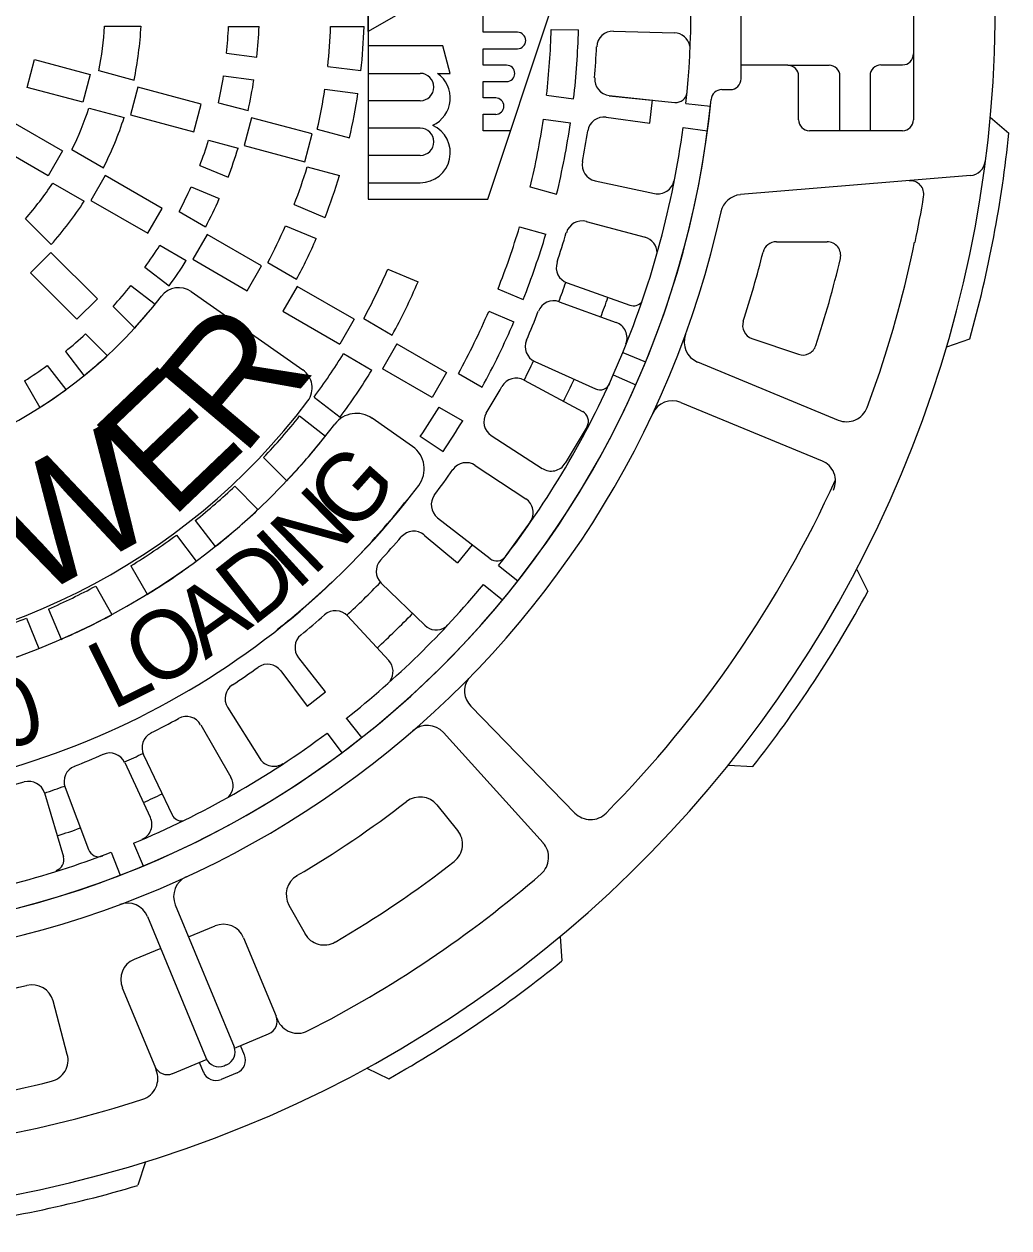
# Model space of a CAD drawing. Extents: x -7.1 to 10, y -5 to 6.
# Drawn here: x -1.07 to -0.132, y -0.445 to 0.702 of the extents above; entities that cross this region are included whole.
import ezdxf

# ---------------------------------------------------------------- set-up
doc = ezdxf.new("R2010")
doc.units = 0
doc.layers.add('Level 1', color=7, linetype='Continuous')

msp = doc.modelspace()

# ---------------------------------------------------------------- linework, layer by layer
at = {"layer": 'Level 1'}
for p, q in [((-0.2233, 0.824), (-0.2233, 0.6105)), ((-0.2233, 0.7612), (-0.2233, 0.6732)), ((-0.7424, 0.7172), (-0.7424, 0.5349)), ((-0.6287, 0.5349), (-0.5679, 0.7172)), ((-0.3874, 0.6496), (-0.3874, 0.7172)), ((-0.9934, 0.6998), (-0.9588, 0.6997)), ((-0.8755, 0.6995), (-0.8464, 0.6995)), ((-0.633, 0.6938), (-0.633, 0.7094)), ((-0.7782, 0.6993), (-0.7464, 0.6992)), ((-0.6003, 0.6938), (-0.633, 0.6938)), ((-0.5682, 0.6966), (-0.5422, 0.6963)), ((-0.5089, 0.6949), (-0.4511, 0.6933)), ((-0.633, 0.6782), (-0.6003, 0.6782)), ((-0.633, 0.6625), (-0.633, 0.6782)), ((-1.0671, 0.6414), (-1.06, 0.6679)), ((-1.06, 0.6679), (-1.0071, 0.6537)), ((-0.8773, 0.6741), (-0.8485, 0.6703)), ((-1.0071, 0.6537), (-1.0142, 0.6273)), ((-0.9988, 0.6573), (-0.9654, 0.6483)), ((-0.7809, 0.6614), (-0.7494, 0.6573)), ((-0.6107, 0.6625), (-0.633, 0.6625)), ((-0.3431, 0.6625), (-0.3874, 0.6625)), ((-0.3431, 0.6625), (-0.3037, 0.6625)), ((-0.2543, 0.6628), (-0.2338, 0.6628)), ((-0.8801, 0.6524), (-0.8513, 0.6486)), ((-0.633, 0.6469), (-0.6107, 0.6469)), ((-0.633, 0.6313), (-0.633, 0.6469)), ((-0.3327, 0.6105), (-0.3327, 0.6521)), ((-0.2933, 0.6), (-0.2933, 0.6521)), ((-0.2647, 0.6524), (-0.2647, 0.6)), ((-1.0142, 0.6273), (-1.0671, 0.6414)), ((-0.9618, 0.6415), (-0.9689, 0.6151)), ((-0.9014, 0.6254), (-0.9618, 0.6415)), ((-0.7837, 0.6397), (-0.7522, 0.6356)), ((-0.6211, 0.6313), (-0.633, 0.6313)), ((-0.5727, 0.634), (-0.5469, 0.6306)), ((-0.513, 0.6336), (-0.4719, 0.6292)), ((-0.513, 0.6334), (-0.4504, 0.627)), ((-0.4057, 0.6392), (-0.3978, 0.6392)), ((-1.0082, 0.6217), (-0.9749, 0.6127)), ((-0.9085, 0.5989), (-0.9014, 0.6254)), ((-0.8849, 0.6268), (-0.8568, 0.6192)), ((-0.4743, 0.6074), (-0.4719, 0.6294)), ((-0.44, 0.626), (-0.4167, 0.6235)), ((-1.0809, 0.6082), (-1.0334, 0.5808)), ((-0.9689, 0.6151), (-0.9085, 0.5989)), ((-0.8536, 0.6125), (-0.8606, 0.5861)), ((-0.7957, 0.597), (-0.8536, 0.6125)), ((-0.633, 0.6157), (-0.6211, 0.6157)), ((-0.633, 0.6), (-0.633, 0.6157)), ((-0.5757, 0.6112), (-0.5499, 0.6077)), ((-0.5159, 0.613), (-0.4743, 0.6074)), ((-0.1502, 0.6131), (-0.1325, 0.5979)), ((-0.8028, 0.5706), (-0.7957, 0.597)), ((-0.791, 0.6016), (-0.7603, 0.5934)), ((-0.607, 0.6), (-0.633, 0.6)), ((-0.4427, 0.6032), (-0.4195, 0.6)), ((-0.2338, 0.6), (-0.3223, 0.6)), ((-0.8945, 0.591), (-0.8663, 0.5834)), ((-0.8606, 0.5861), (-0.8028, 0.5706)), ((-1.0471, 0.5571), (-1.0945, 0.5845)), ((-1.0334, 0.5808), (-1.0471, 0.5571)), ((-1.0245, 0.5821), (-0.9945, 0.5648)), ((-0.9028, 0.5669), (-0.8759, 0.5558)), ((-0.8005, 0.5656), (-0.7699, 0.5573)), ((-0.9928, 0.5573), (-1.0065, 0.5337)), ((-0.9387, 0.5261), (-0.9928, 0.5573)), ((-0.5264, 0.5524), (-0.4699, 0.5403)), ((-0.1692, 0.5574), (-0.388, 0.5392)), ((-1.0428, 0.5502), (-1.0129, 0.5329)), ((-0.9111, 0.5467), (-0.8842, 0.5356)), ((-0.5882, 0.5465), (-0.5631, 0.5396)), ((-1.0065, 0.5337), (-0.9523, 0.5024)), ((-0.813, 0.5297), (-0.7836, 0.5175)), ((-0.7424, 0.5349), (-0.6287, 0.5349)), ((-1.0688, 0.5162), (-1.0443, 0.4917)), ((-0.9523, 0.5024), (-0.9387, 0.5261)), ((-0.9224, 0.5232), (-0.8972, 0.5086)), ((-0.8213, 0.5095), (-0.7919, 0.4973)), ((-0.5984, 0.5086), (-0.5733, 0.5016)), ((-0.5348, 0.5137), (-0.4789, 0.4987)), ((-0.8958, 0.5013), (-0.9095, 0.4776)), ((-0.8439, 0.4714), (-0.8958, 0.5013)), ((-0.3539, 0.4943), (-0.3056, 0.4943)), ((-1.0446, 0.484), (-1.0639, 0.4647)), ((-1.0003, 0.4398), (-1.0446, 0.484)), ((-0.9408, 0.4911), (-0.9157, 0.4765)), ((-0.9095, 0.4776), (-0.8576, 0.4477)), ((-0.8576, 0.4477), (-0.8439, 0.4714)), ((-0.8381, 0.4745), (-0.8106, 0.4586)), ((-1.0639, 0.4647), (-1.0197, 0.4205)), ((-0.9551, 0.47), (-0.9321, 0.4523)), ((-0.7238, 0.4683), (-0.695, 0.4562)), ((-0.9684, 0.4526), (-0.9453, 0.4349)), ((-0.81, 0.4518), (-0.8237, 0.4281)), ((-0.7559, 0.4206), (-0.81, 0.4518)), ((-0.6189, 0.4494), (-0.5949, 0.4394)), ((-0.553, 0.4551), (-0.4933, 0.4339)), ((-1.0197, 0.4205), (-1.0003, 0.4398)), ((-0.9109, 0.4468), (-0.8046, 0.3724)), ((-0.5606, 0.4372), (-0.5063, 0.4175)), ((-0.9854, 0.4328), (-0.9648, 0.4122)), ((-0.8237, 0.4281), (-0.7696, 0.3969)), ((-0.8237, 0.4281), (-0.7696, 0.3969)), ((-0.6277, 0.4281), (-0.6037, 0.418)), ((-0.7559, 0.4206), (-0.7696, 0.3969)), ((-0.7467, 0.4211), (-0.7197, 0.4054)), ((-1.0115, 0.4066), (-0.991, 0.3859)), ((-0.3773, 0.4022), (-0.3329, 0.3871)), ((-0.1917, 0.3943), (-0.1697, 0.4019)), ((-1.0308, 0.3899), (-1.0131, 0.3668)), ((-0.7153, 0.3971), (-0.729, 0.3734)), ((-0.7153, 0.3971), (-0.6679, 0.3698)), ((-0.766, 0.3878), (-0.739, 0.372)), ((-0.5838, 0.3803), (-0.5261, 0.3541)), ((-0.5092, 0.3677), (-0.5001, 0.3888)), ((-0.5001, 0.3888), (-0.4785, 0.3799)), ((-0.4288, 0.3798), (-0.2949, 0.3244)), ((-1.0481, 0.3766), (-1.0304, 0.3535)), ((-0.6816, 0.3461), (-0.729, 0.3734)), ((-0.6679, 0.3698), (-0.6816, 0.3461)), ((-0.6566, 0.3688), (-0.6341, 0.3557)), ((-0.5092, 0.3677), (-0.4878, 0.3582)), ((-1.0696, 0.3618), (-1.0551, 0.3366)), ((-0.594, 0.3626), (-0.5383, 0.3325)), ((-0.2674, 0.3365), (-0.2582, 0.3621)), ((-0.794, 0.3464), (-0.7692, 0.3274)), ((-0.6751, 0.3367), (-0.6525, 0.3238)), ((-0.4448, 0.3413), (-0.3104, 0.2857)), ((-0.8078, 0.3284), (-0.7831, 0.3093)), ((-0.7002, 0.2993), (-0.7386, 0.3262)), ((-0.6253, 0.3097), (-0.5767, 0.2784)), ((-0.5341, 0.3183), (-0.5549, 0.2833)), ((-0.6929, 0.309), (-0.6712, 0.2946)), ((-0.8421, 0.2888), (-0.82, 0.2666)), ((-0.6405, 0.2813), (-0.5923, 0.2494)), ((-0.8693, 0.2616), (-0.8474, 0.2393)), ((-0.6764, 0.2315), (-0.6265, 0.1925)), ((-0.9071, 0.2288), (-0.8881, 0.204)), ((-0.6118, 0.1944), (-0.5881, 0.2275)), ((-0.9251, 0.215), (-0.9062, 0.1901)), ((-0.6891, 0.215), (-0.6574, 0.1885)), ((-0.6434, 0.2057), (-0.6574, 0.1885)), ((-0.9685, 0.1856), (-0.9529, 0.1585)), ((-0.6184, 0.1859), (-0.5999, 0.1715)), ((-0.2773, 0.1821), (-0.2668, 0.1613)), ((-1.0018, 0.1664), (-0.9865, 0.1392)), ((-0.7301, 0.1692), (-0.6886, 0.129)), ((-0.6328, 0.168), (-0.6147, 0.1531)), ((-1.0468, 0.1445), (-1.0349, 0.1157)), ((-0.7622, 0.1379), (-0.7229, 0.0954)), ((-1.0678, 0.1358), (-1.0559, 0.1069)), ((-0.8089, 0.098), (-0.7833, 0.0655)), ((-0.8257, 0.0857), (-0.8006, 0.052)), ((-0.8006, 0.052), (-0.7831, 0.0657)), ((-0.8763, 0.0509), (-0.8455, 0.002)), ((-0.5458, -0.0498), (-0.6449, 0.052)), ((-0.7633, 0.0404), (-0.7488, 0.022)), ((-0.9019, 0.0343), (-0.8731, -0.0158)), ((-0.7816, 0.0264), (-0.7675, 0.0076)), ((-0.6707, 0.0269), (-0.576, -0.0782)), ((-0.9563, 0.0057), (-0.9291, -0.0515)), ((-0.9743, -0.0016), (-0.9499, -0.0539)), ((-0.3994, -0.0041), (-0.3762, -0.0055)), ((-1.0507, -0.0307), (-1.0326, -0.0914)), ((-1.031, -0.0254), (-1.0087, -0.0847)), ((-0.677, -0.0421), (-0.6573, -0.0663)), ((-0.9658, -0.0785), (-0.9568, -0.1002)), ((-0.9871, -0.0871), (-0.9787, -0.1089)), ((-0.9262, -0.1374), (-0.8702, -0.2725)), ((-0.9526, -0.1485), (-0.8967, -0.2835)), ((-0.8179, -0.1376), (-0.8026, -0.1649)), ((-0.9136, -0.1678), (-0.8883, -0.1573)), ((-0.8611, -0.1686), (-0.8302, -0.2432)), ((-0.5598, -0.1674), (-0.558, -0.1907)), ((-0.94, -0.1788), (-0.9653, -0.1892)), ((-0.9766, -0.2164), (-0.9457, -0.291)), ((-1.0289, -0.2797), (-1.0425, -0.2288)), ((-0.8297, -0.2447), (-0.8288, -0.2468)), ((-0.8697, -0.2737), (-0.8373, -0.2602)), ((-0.8603, -0.2803), (-0.864, -0.2713)), ((-0.8962, -0.2846), (-0.9287, -0.2981)), ((-0.9457, -0.291), (-0.9442, -0.2946)), ((-0.8994, -0.2965), (-0.9031, -0.2875)), ((-0.8673, -0.2973), (-0.8824, -0.3035)), ((-0.8784, -0.2901), (-0.8785, -0.2901)), ((-0.7438, -0.2927), (-0.7229, -0.3029)), ((-0.9544, -0.3822), (-0.9617, -0.4044))]:
    msp.add_line(p, q, dxfattribs=at)
for points in [[(-0.7424, 0.7807), (-0.7424, 0.8108), (-0.6643, 0.7657), (-0.6643, 0.7397), (-0.7424, 0.6946), (-0.7424, 0.7246)], [(-0.6765, 0.6547), (-0.6643, 0.6547), (-0.6713, 0.6808), (-0.7424, 0.6808), (-0.7424, 0.6547), (-0.6929, 0.6547)], [(-0.7424, 0.6287), (-0.7424, 0.6027), (-0.6929, 0.6027)], [(-0.6929, 0.6287), (-0.7424, 0.6287)], [(-0.6929, 0.5766), (-0.7424, 0.5766), (-0.7424, 0.5506), (-0.6929, 0.5506)]]:
    msp.add_lwpolyline(points, dxfattribs=at)
for centre, radius, start, end in [((-1.2973, 0.7173), 1.1516, 195.0717, 189.1227), ((-1.2971, 0.7172), 0.862, 353.922, 6.078), ((-1.2971, 0.7172), 0.3042, 348.6342, 356.7065), ((-1.2971, 0.7172), 0.3388, 348.2633, 357.0305), ((-1.2971, 0.7172), 0.422, 354.1323, 357.593), ((-1.2971, 0.7172), 0.4511, 354.027, 357.7407), ((-1.2971, 0.7172), 0.5192, 353.8266, 358.0217), ((-1.2971, 0.7172), 0.551, 353.7501, 358.129), ((-0.6003, 0.686), 0.00781, 269.9991, 89.9991), ((-1.2971, 0.7172), 0.7292, 353.4475, 358.3753), ((-1.2971, 0.7172), 0.7552, 353.415, 358.4128), ((-0.5093, 0.6793), 0.0156, 88.389, 177.2537), ((-0.4515, 0.6777), 0.0156, 11.1758, 88.389), ((-1.297, 0.7171), 0.7729, 355.0578, 357.2537), ((-0.2338, 0.6732), 0.0104, 270, 0), ((-0.6929, 0.6417), 0.013, 270, 90), ((-0.6929, 0.6313), 0.0286, 294.62, 54.9032), ((-0.6107, 0.6547), 0.00781, 269.9991, 89.9991), ((-0.3431, 0.6521), 0.0104, 0, 90), ((-0.3037, 0.6521), 0.0104, 0, 90), ((-0.2543, 0.6524), 0.0104, 90, 180), ((-1.2971, 0.7172), 0.8854, 184.6051, 354.3326), ((-1.2971, 0.7172), 0.422, 347.6194, 351.1618), ((-1.2971, 0.7172), 0.4511, 347.4503, 351.2482), ((-0.5113, 0.6492), 0.0156, 175.0578, 263.9224), ((-0.3978, 0.6496), 0.0104, 270, 0), ((-1.2971, 0.7172), 0.5192, 347.1287, 351.4124), ((-1.2971, 0.7172), 0.551, 347.0059, 351.4752), ((-0.6211, 0.6235), 0.00781, 269.9991, 89.9991), ((-0.4493, 0.6374), 0.0104, 264.177, 354.6212), ((-0.4057, 0.6288), 0.0104, 90, 174.3326), ((-1.2971, 0.7172), 0.8854, 272.6352, 354.3326), ((-1.2971, 0.7172), 0.3042, 333.6342, 341.7065), ((-1.2971, 0.7172), 0.3388, 333.2633, 342.0305), ((-1.2971, 0.7172), 0.7292, 346.4545, 351.638), ((-0.518, 0.5975), 0.0156, 82.3944, 171.2591), ((-0.3223, 0.6105), 0.0104, 180, 270), ((-0.2338, 0.6105), 0.0104, 270, 0), ((-0.6929, 0.5792), 0.0286, 270, 65.38), ((-0.6929, 0.5896), 0.013, 270, 90), ((-1.2971, 0.7172), 0.7552, 346.3995, 351.6608), ((-1.2974, 0.7173), 0.7729, 349.0632, 351.2591), ((-1.2971, 0.7172), 0.862, 337.6056, 352.3944), ((-1.2966, 0.7177), 1.1703, 344.3462, 354.1251), ((-1.2971, 0.7172), 0.9115, 188.0305, 347.6848), ((-1.2971, 0.7172), 0.422, 339.1323, 342.593), ((-1.2971, 0.7172), 0.4511, 339.027, 342.7407), ((-1.2971, 0.7172), 0.5192, 338.8266, 343.0217), ((-0.5232, 0.5677), 0.0156, 169.0632, 257.9278), ((-0.1705, 0.5729), 0.0156, 274.7589, 352.7027), ((-1.2971, 0.7172), 0.551, 338.7501, 343.129), ((-0.4666, 0.5556), 0.0156, 257.9278, 348.9856), ((-0.2265, 0.5395), 0.013, 350.5705, 94.7589), ((-1.2971, 0.7172), 0.3042, 318.6342, 326.7065), ((-1.2971, 0.7172), 0.422, 332.6194, 336.1618), ((-0.3863, 0.5184), 0.0208, 94.7589, 167.6848), ((-1.2971, 0.7172), 0.3388, 318.2633, 327.0305), ((-1.2971, 0.7172), 0.4511, 332.4503, 336.2482), ((-1.2971, 0.7173), 1.0983, 348.257, 350.5705), ((-1.2971, 0.7172), 0.5192, 332.1287, 336.4124), ((-1.2971, 0.7172), 0.7292, 338.4475, 343.3753), ((-0.5388, 0.4986), 0.0156, 74.9422, 163.8068), ((-1.2971, 0.7172), 0.551, 332.0059, 336.4752), ((-1.2971, 0.7172), 0.7552, 338.415, 343.4128), ((-1.2961, 0.7186), 0.7729, 341.6109, 343.8068), ((-0.483, 0.4836), 0.0156, 0.2442, 74.9422), ((-0.3539, 0.4813), 0.013, 90, 166.0155), ((-0.3056, 0.4813), 0.013, 346.6473, 90), ((-1.2967, 0.7161), 1.0972, 341.1743, 348.3154), ((-1.2971, 0.7172), 0.422, 324.1323, 327.593), ((-1.2967, 0.7161), 0.9586, 341.9169, 346.0155), ((-1.2971, 0.7172), 0.4511, 324.027, 327.7407), ((-0.5478, 0.4698), 0.0156, 161.6109, 250.4756), ((-1.2975, 0.7168), 1.0325, 341.862, 346.6473), ((-1.2971, 0.7172), 0.625, 331.7203, 336.5279), ((-1.2971, 0.7172), 0.422, 317.6194, 321.1618), ((-0.9229, 0.4298), 0.0208, 55, 142.4698), ((-1.2971, 0.7172), 0.6563, 331.6317, 336.5646), ((-1.2971, 0.7172), 0.7875, 339.1803, 340.5909), ((-1.2971, 0.7172), 0.4511, 217.5302, 322.4698), ((-0.5659, 0.4225), 0.0156, 70.0352, 158.8998), ((-1.2971, 0.7172), 0.8301, 339.2248, 340.5852), ((-0.4898, 0.4437), 0.0104, 250.4756, 318.3766), ((-1.2971, 0.7172), 0.4511, 317.4503, 321.2482), ((-1.2971, 0.7172), 0.7292, 331.4545, 336.638), ((-1.3016, 0.7064), 0.7729, 336.704, 338.8998), ((-1.2971, 0.7172), 0.7552, 331.3995, 336.6608), ((-0.5116, 0.4028), 0.0156, 338.9774, 70.0352), ((-0.373, 0.4145), 0.013, 161.9169, 251.149), ((-1.2971, 0.7172), 0.422, 309.1323, 312.593), ((-0.4209, 0.399), 0.0208, 160.1115, 247.5378), ((-0.5774, 0.3945), 0.0156, 156.704, 245.5686), ((-0.3287, 0.3994), 0.013, 251.149, 341.862), ((-1.2971, 0.7172), 0.4511, 309.027, 312.7407), ((-1.2971, 0.7172), 0.625, 323.6043, 328.1939), ((-1.2971, 0.7172), 0.7875, 333.2323, 334.7184), ((-1.2971, 0.7172), 0.422, 302.6194, 306.1618), ((-0.8166, 0.3553), 0.0208, 323.0153, 55), ((-1.2971, 0.7172), 0.6563, 323.552, 328.2544), ((-1.2971, 0.7172), 0.862, 321.9456, 336.078), ((-1.2881, 0.7366), 0.7729, 328.3474, 330.5433), ((-0.6015, 0.3488), 0.0156, 61.6787, 150.5433), ((-1.2971, 0.7172), 0.8301, 333.1524, 334.7577), ((-0.5218, 0.3636), 0.0104, 245.5686, 336.2781), ((-1.2971, 0.7172), 0.4511, 302.4503, 306.2482), ((-1.2971, 0.7172), 0.6224, 216.9847, 323.0153), ((-1.2971, 0.7172), 0.7292, 325.9538, 328.5455), ((-0.4528, 0.322), 0.0208, 67.5378, 154.8411), ((-0.287, 0.3437), 0.0208, 247.5378, 339.8014), ((-1.2971, 0.7172), 0.625, 316.7203, 321.5279), ((-0.7536, 0.3048), 0.026, 55, 142.8126), ((-1.2971, 0.7172), 0.7552, 325.9699, 328.6005), ((-0.6168, 0.3228), 0.0156, 148.3474, 237.2121), ((-0.5432, 0.3234), 0.0104, 330.9692, 61.6787), ((-1.2971, 0.7172), 0.6562, 217.1874, 322.8126), ((-1.2971, 0.7172), 0.6563, 316.6317, 321.5646), ((-0.7151, 0.2779), 0.026, 322.9239, 55), ((-1.2972, 0.7175), 0.7729, 323.0809, 325.2768), ((-0.6491, 0.2683), 0.0156, 56.4122, 145.2768), ((-0.5682, 0.2915), 0.0156, 237.2121, 328.2699), ((-0.3184, 0.2665), 0.0208, 335.2566, 67.5378), ((-1.2976, 0.7218), 1.0983, 315.3646, 335.5685), ((-1.2973, 0.7178), 0.7557, 217.0904, 322.9239), ((-1.2971, 0.7172), 0.625, 308.6043, 313.1939), ((-0.6668, 0.2438), 0.0156, 143.0809, 231.9456), ((-1.2974, 0.7174), 0.7552, 316.3995, 321.6608), ((-0.601, 0.2364), 0.0156, 325.3544, 56.4122), ((-1.2971, 0.7172), 0.6563, 308.552, 313.2544), ((-0.6991, 0.203), 0.0156, 50.4176, 139.2822), ((-1.2971, 0.7172), 0.625, 301.7203, 306.5279), ((-1.2968, 0.7174), 0.7729, 317.0863, 319.2822), ((-1.2971, 0.7172), 0.6563, 301.6317, 306.5646), ((-0.7192, 0.1804), 0.0156, 137.0863, 225.951), ((-0.6201, 0.2007), 0.0104, 231.9456, 322.6551), ((-1.2971, 0.7172), 0.625, 293.6043, 298.1939), ((-1.2973, 0.7175), 0.7552, 308.3235, 313.5848), ((-1.2971, 0.7172), 0.862, 308.262, 320.418), ((-1.2971, 0.7172), 0.7875, 312.7158, 315.9774), ((-1.2965, 0.7174), 1.1703, 321.8462, 331.6251), ((-1.2971, 0.7172), 0.6563, 293.552, 298.2544), ((-1.2971, 0.717), 0.7729, 309.3978, 311.5937), ((-0.7736, 0.1273), 0.0156, 42.729, 131.5937), ((-1.2971, 0.7172), 0.8301, 312.7192, 315.9733), ((-1.2971, 0.7172), 0.625, 286.7203, 291.5279), ((-0.6777, 0.1402), 0.0156, 225.951, 303.1642), ((-0.7966, 0.1077), 0.0156, 129.3978, 218.2624), ((-1.2971, 0.7172), 0.6563, 286.6317, 291.5646), ((-0.8382, 0.0763), 0.0156, 36.7344, 125.5991), ((-0.7344, 0.0848), 0.0156, 325.5158, 42.729), ((-1.2972, 0.7175), 0.7729, 303.4032, 305.5991), ((-0.8631, 0.0592), 0.0156, 123.4032, 212.2678), ((-0.6299, 0.0665), 0.0208, 145.8214, 224.2281), ((-1.2955, 0.7175), 0.7729, 296.6109, 298.8068), ((-0.9155, 0.0265), 0.0156, 29.9422, 118.8068), ((-1.2971, 0.7172), 0.862, 292.6056, 306.7344), ((-0.9422, 0.0124), 0.0156, 116.6109, 205.4756), ((-0.6862, 0.0129), 0.0208, 42.022, 131.4737), ((-1.308, 0.7128), 0.7729, 291.704, 293.8998), ((-0.9885, -0.0082), 0.0156, 25.0352, 113.8998), ((-1.2971, 0.7172), 0.7875, 294.1803, 295.5909), ((-0.8323, 0.0103), 0.0156, 212.2678, 303.3256), ((-1.0164, -0.0199), 0.0156, 111.704, 200.5686), ((-1.277, 0.7246), 0.7729, 283.3474, 285.5433), ((-1.0657, -0.0352), 0.0156, 16.6787, 105.5433), ((-0.8866, -0.0236), 0.0156, 315.2442, 29.9422), ((-1.2971, 0.7172), 0.7875, 288.2323, 289.7184), ((-1.2971, 0.7172), 0.8301, 294.2248, 295.5852), ((-1.2976, 0.7217), 0.9635, 300.3841, 307.8801), ((-0.6931, -0.0553), 0.0208, 39.1639, 127.8801), ((-0.964, -0.0606), 0.0156, 293.9774, 25.0352), ((-0.9197, -0.047), 0.0104, 205.4756, 273.3766), ((-0.5308, -0.0353), 0.0208, 224.2281, 315.3646), ((-1.2971, 0.7172), 0.8301, 288.1524, 289.7577), ((-0.6734, -0.0795), 0.0208, 307.9191, 39.1639), ((-0.5915, -0.0921), 0.0208, 310.9426, 42.022), ((-1.2971, 0.7172), 0.862, 277.6056, 291.078), ((-1.0425, -0.0944), 0.0104, 285.9692, 16.6787), ((-0.999, -0.081), 0.0104, 200.5686, 291.2781), ((-1.2976, 0.7217), 1.0365, 300.3463, 307.9191), ((-0.9069, -0.1294), 0.0208, 114.807, 202.5), ((-0.7997, -0.1275), 0.0208, 120.3841, 209.1622), ((-1.2976, 0.7218), 1.0983, 296.9323, 310.9426), ((-0.9718, -0.1564), 0.0208, 22.5, 110.3605), ((-0.8803, -0.1766), 0.0208, 22.5, 112.5), ((-0.7845, -0.1547), 0.0208, 209.1622, 300.3463), ((-0.9573, -0.2085), 0.0208, 112.5, 202.5), ((-1.2965, 0.7172), 1.1703, 299.3462, 309.1251), ((-1.2976, 0.7217), 0.9635, 276.5447, 283.807), ((-1.0626, -0.2342), 0.0208, 15.0206, 103.807), ((-0.8422, -0.2482), 0.013, 292.5, 22.5), ((-0.8096, -0.2388), 0.0208, 202.5, 296.9323), ((-0.8822, -0.2775), 0.013, 292.5706, 22.5), ((-1.049, -0.2851), 0.0208, 283.9682, 15.0206), ((-0.8846, -0.2785), 0.013, 202.5, 292.4327), ((-0.8723, -0.2852), 0.013, 292.5, 22.5), ((-0.9635, -0.3026), 0.0208, 288.0661, 22.5), ((-0.9337, -0.286), 0.013, 202.5, 292.5), ((-0.8874, -0.2915), 0.013, 202.5, 292.5), ((-1.2976, 0.7217), 1.0951, 292.4327, 292.5706), ((-1.2986, 0.7183), 1.0548, 276.5594, 283.9682), ((-1.2976, 0.7218), 1.0983, 272.2423, 288.0661), ((-1.2965, 0.7169), 1.1703, 276.8462, 286.6251)]:
    msp.add_arc(centre, radius, start, end, dxfattribs=at)

# ---------------------------------------------------------------- texts
for s, height, rotation, p in [('R', 0.1144, 49.9036, (-0.8626, 0.288)), ('E', 0.1144, 43.6991, (-0.9309, 0.2284)), ('W', 0.1144, 29.0041, (-1.0617, 0.1527)), ('G', 0.0651, 48.481, (-0.7571, 0.2137)), ('N', 0.0651, 44.571, (-0.7951, 0.1747)), ('I', 0.0651, 42.2853, (-0.8108, 0.1609)), ('D', 0.0651, 38.1524, (-0.8531, 0.1267)), ('A', 0.0651, 35.5388, (-0.8975, 0.0954)), ('O', 0.0651, 33.0612, (-0.947, 0.0653)), ('L', 0.0651, 26.334, (-0.9863, 0.0477)), ('0', 0.0651, 17.3354, (-1.0927, 0.0086))]:
    msp.add_text(s, height=height, rotation=rotation, dxfattribs=at).set_placement(p)

doc.saveas('drawing.dxf')
